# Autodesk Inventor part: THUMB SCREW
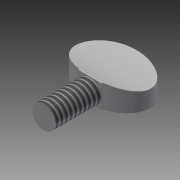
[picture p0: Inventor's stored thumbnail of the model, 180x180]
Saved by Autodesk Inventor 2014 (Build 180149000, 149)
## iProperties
Shininess: 64.0
Length Units: 11272
Angle Units: 11279
Time Units: 11290
Mass Units: 11286
Length Display Precision: 3
Angle Display Precision: 2
Compacted: True
Part Number: THUMB SCREW
Document SubType Name: Modeling
Created: 2003-11
Designer: Autodesk, Inc.
Manufacturer: Standard
Standards Organization: Custom
Mass: 11.3688 g
Surface Area: 9.71998 cm^2
Volume: 1.44641 cm^3
Density: 7.86 g/cm^3
Material: Steel, Mild
Appearance: Steel
Density: 0.0
Volumn: 0.0
Area: 0.0
PropertySet Name: Model Information
Control State: 0
Master: False
Checked Out: False
Author: Autodesk, Inc.
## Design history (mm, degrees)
sketch "Sketch1"
  geometry: C1 r 3.175 at (0, 0); 1 further point
  constraints: 1 centre point, 1 coincident
  dimensions: "d0" = 6.35 diameter of C1
extrude "Extrusion1" new body sketch "Sketch1" distance "d1" = 12.7; taper "d2" = 0 deg
sketch "Sketch2"
  geometry: L1 (-10.312, 3.175)-(10.312, 3.175); L2 (10.312, 3.175)-(10.312, -3.175); L3 (10.312, -3.175)-(-10.312, -3.175); L4 (-10.312, -3.175)-(-10.312, 3.175); C1 r 3.175 at (0, 0) reference; 1 further point
  constraints: 8 end point, 2 parallel, 1 horizontal, 1 perpendicular
  dimensions: "d3" = 3.175 distance from line of L3 point (0, 0); "d4" = 3.175 distance from line of point (0, 0) L1; "d5" = 20.6248 distance between parallel lines of L2 L4; "d6" = 10.3124 distance from line of L4 point (0, 0) (= 0.5 x d5)
extrude "Extrusion2" join sketch "Sketch2" distance "d7" = 12.7; taper "d8" = 0 deg
sketch "Sketch3"
  geometry: L1 (20.625, 12.7)-(0, 12.7) reference; L2 (0, 0)-(0, 12.7) reference; L3 (10.312, 0)-(0, 0) reference; L4 (20.625, 0)-(10.312, 0) reference; L5 (20.625, 0)-(20.625, 12.7) reference; L6 (10.312, 12.7)-(10.312, 0); L7 (0, 6.35)-(20.625, 6.35); L8 (7.137, 0)-(7.137, -12.7) reference; L9 (13.487, 0)-(13.487, -12.7) reference; L10 (7.137, 0)-(7.137, 0.308); L11 (13.487, 0)-(13.487, 0.308); 1 further point; 1 other entity
  constraints: 8 end point, 4 midpoint, 3 vertical, 1 parallel, 6 other
extrude "Extrusion3" cut sketch "Sketch3" distance "d9" = 12.7; taper "d10" = 0 deg
workplane "Work Plane1"
sketch "Sketch4"
  geometry: L1 (-3.175, -0.308)-(-3.175, -0.308) reference; L2 (3.175, -0.308)-(-3.175, -0.308) reference; L3 (3.175, -0.308)-(3.175, -0.308) reference; L4 (3.175, -0.308)-(-3.175, -0.308) reference; L5 (-3.175, -0.308)-(-3.175, -12.7) reference; L6 (3.175, -12.7)-(3.175, -0.308) reference; L7 (3.175, -12.7)-(3.175, -0.308); L8 (-3.175, -0.308)-(-3.175, -12.7); A1 r 22.382 centre (-24.682, -6.504) between (-3.175, -12.7) and (-3.175, -0.308); A2 r 22.382 centre (24.682, -6.504) between (3.175, -0.308) and (3.175, -12.7)
  constraints: 4 end point, 4 point on circle, 2 centre point, 2 equal length
  dimensions: "d12" = 22.38154 radius of A1; "d13" = 22.38154 radius of A2 (= d12)
extrude "Extrusion4" cut sketch "Sketch4" distance "d14" = 25.4; taper "d15" = 0 deg
thread "Thread1" dims "d16" = 25.4, "d17" = 0
body "Solid1"
node "Projected Loop1"
node "Projected Loop2"
other parameters: "d11" = -12.7
